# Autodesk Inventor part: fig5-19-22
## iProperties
Created: 2004-05
Part Number: fig5-19-22
Document SubType Name: Modeling
Designer: CADCIM Technologies
Manufacturer: Standard
Standards Organization: Custom
Density: 1 g/cm^3
Author: CADCIM Technologies
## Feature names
1. Extrusion1
2. Fillet6
